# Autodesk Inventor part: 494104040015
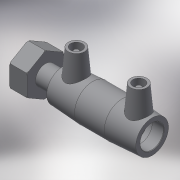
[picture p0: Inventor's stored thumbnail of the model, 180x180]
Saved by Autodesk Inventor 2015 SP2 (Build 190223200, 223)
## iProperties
Created: 2017-06
Part Number: 494104040015
Material: Generic
Description: PLASSON FEMALE FREE NUT TRANSITION COUPLER 32-1.1/4"
Document SubType Name: Modeling
Designer: KIM
Mass: 55.0731 g
Surface Area: 148.067 cm^2
Volume: 55.0731 cm^3
Density: 1 g/cm^3
Appearance: Default
Author: KIM
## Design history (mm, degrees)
derived "494104.ipt"
feature "Solid1::494104.ipt"
tag "TaggingFeature1"
body "Solid1"
other parameters: "d0" = 97, "d2" = 56, "d3" = 47, "d4" = 32.33333, "d5" = 50.4, "d6" = 38, "d8" = 168 deg, "d10" = 18.8, "d11" = 6.26667, "d29" = 45, "d30" = 14, "d31" = 33.95, "d34" = 5 deg, "d41" = 4, "d42" = 14, "d43" = 0, "d48" = 3, "d49" = 0, "d55" = 38, "d57" = 29, "d80" = 0.8, "d83" = 19, "d84" = 12.54, "d85" = 1.254, "d86" = 35.876, "d87" = 44.845, "d88" = 67.2675, "d89" = 56, "d90" = 1.34535, "d94" = 0, "d95" = 1.254, "d96" = 31.3915, "L_" = 135, "L_1" = 47, "D_1" = 56, "A_" = 45, "d_2" = 12, "L_2" = 38, "D_" = 29, "G_" = 44.845
